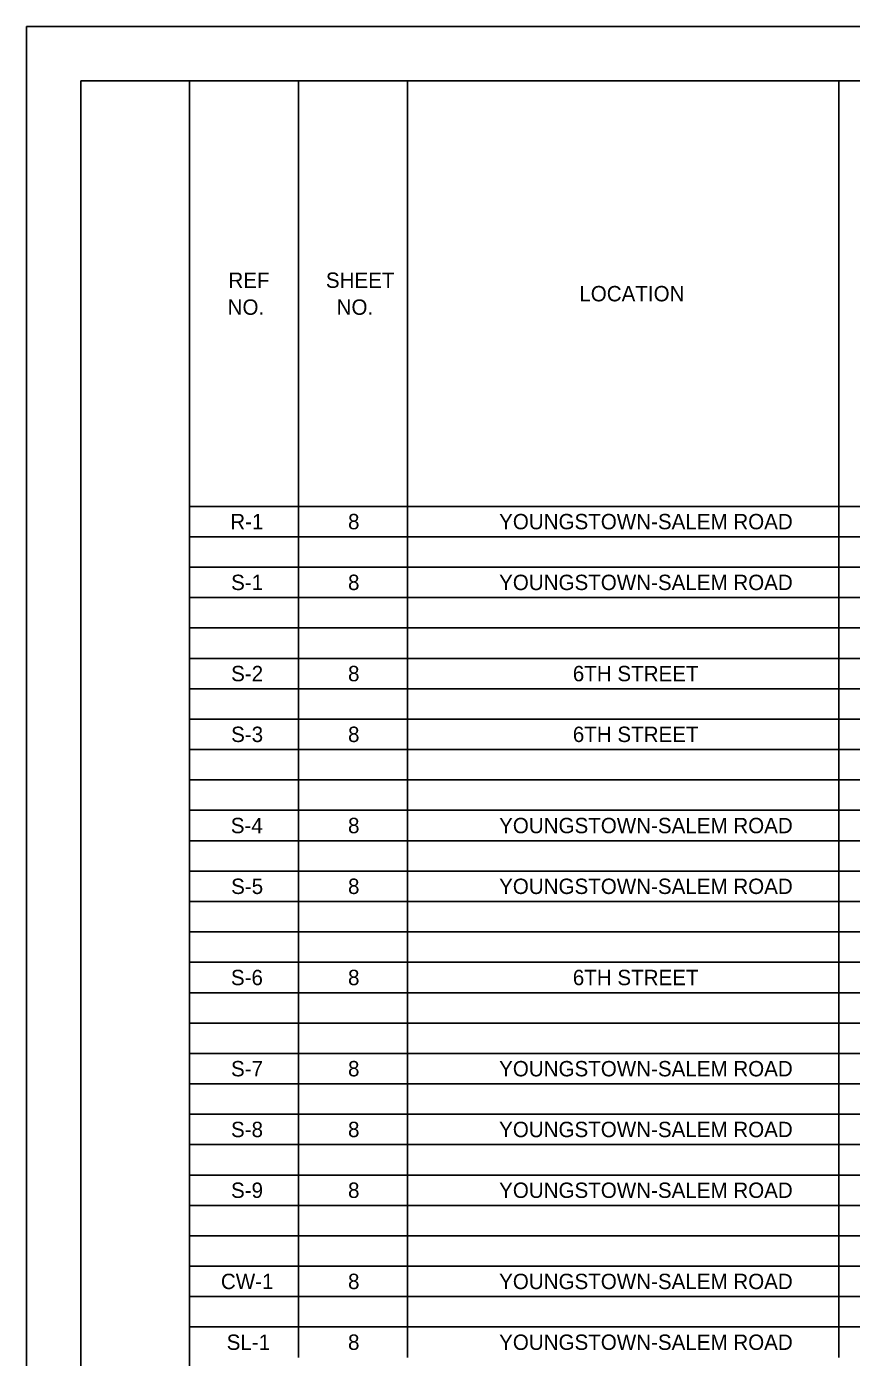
# Model space of a CAD drawing. Extents: x 0 to 34, y 0 to 22.
# Drawn here: x 0 to 7.6, y 9.74 to 22 of the extents above; entities that cross this region are included whole.
import ezdxf

# ---------------------------------------------------------------- set-up
doc = ezdxf.new("R2010")
doc.units = 0
for name, color, linetype in [('SH_Border', 7, 'Continuous'), ('SH_Cut_Line', 7, 'Continuous'), ('SH_Data', 7, 'Continuous')]:
    doc.layers.add(name, color=color, linetype=linetype)

msp = doc.modelspace()

# ---------------------------------------------------------------- linework, layer by layer
at = {"layer": 'SH_Border'}
for points in [[(0.5, 21.5), (1.5, 21.5), (1.5, 0.5), (0.5, 0.5)], [(1.5, 21.5), (33.5, 21.5), (33.5, 0.5), (1.5, 0.5)]]:
    msp.add_lwpolyline(points, close=True, dxfattribs=at)
at = {"layer": 'SH_Cut_Line'}
msp.add_lwpolyline([(0, 0), (34, 0), (34, 22), (0, 22)], close=True, dxfattribs=at)
at = {"layer": 'SH_Data'}
for p, q in [((1.5, 21.5), (8.951, 21.5)), ((1.5, 21.5), (1.5, 21.22)), ((2.504, 21.5), (2.504, 21.22)), ((3.508, 21.5), (3.508, 21.22)), ((7.484, 21.5), (7.484, 21.22)), ((1.5, 21.22), (1.5, 20.94)), ((2.504, 21.22), (2.504, 20.94)), ((3.508, 21.22), (3.508, 20.94)), ((7.484, 21.22), (7.484, 20.94)), ((1.5, 20.94), (1.5, 20.66)), ((2.504, 20.94), (2.504, 20.66)), ((3.508, 20.94), (3.508, 20.66)), ((7.484, 20.94), (7.484, 20.66)), ((1.5, 20.66), (1.5, 20.38)), ((2.504, 20.66), (2.504, 20.38)), ((3.508, 20.66), (3.508, 20.38)), ((7.484, 20.66), (7.484, 20.38)), ((1.5, 20.38), (1.5, 20.1)), ((2.504, 20.38), (2.504, 20.1)), ((3.508, 20.38), (3.508, 20.1)), ((7.484, 20.38), (7.484, 20.1)), ((1.5, 20.1), (1.5, 19.82)), ((2.504, 20.1), (2.504, 19.82)), ((3.508, 20.1), (3.508, 19.82)), ((7.484, 20.1), (7.484, 19.82)), ((1.5, 19.82), (1.5, 19.54)), ((2.504, 19.82), (2.504, 19.54)), ((3.508, 19.82), (3.508, 19.54)), ((7.484, 19.82), (7.484, 19.54)), ((1.5, 19.54), (1.5, 18.98)), ((2.504, 19.54), (2.504, 18.98)), ((3.508, 19.54), (3.508, 18.98)), ((7.484, 19.54), (7.484, 18.98)), ((1.5, 18.98), (1.5, 18.14)), ((2.504, 18.98), (2.504, 18.14)), ((3.508, 18.98), (3.508, 18.14)), ((7.484, 18.98), (7.484, 18.14)), ((1.5, 18.14), (1.5, 17.86)), ((2.504, 18.14), (2.504, 17.86)), ((3.508, 18.14), (3.508, 17.86)), ((7.484, 18.14), (7.484, 17.86)), ((1.5, 17.86), (1.5, 17.3)), ((2.504, 17.86), (2.504, 17.3)), ((3.508, 17.86), (3.508, 17.3)), ((7.484, 17.86), (7.484, 17.3)), ((1.5, 17.58), (8.951, 17.58)), ((1.5, 17.3), (8.951, 17.3)), ((1.5, 17.3), (1.5, 17.02)), ((2.504, 17.3), (2.504, 17.02)), ((3.508, 17.3), (3.508, 17.02)), ((7.484, 17.3), (7.484, 17.02)), ((1.5, 17.02), (8.951, 17.02)), ((1.5, 17.02), (1.5, 15.9)), ((2.504, 17.02), (2.504, 15.9)), ((3.508, 17.02), (3.508, 15.9)), ((7.484, 17.02), (7.484, 15.9)), ((1.5, 16.74), (8.951, 16.74)), ((1.5, 16.46), (8.951, 16.46)), ((1.5, 16.18), (8.951, 16.18)), ((1.5, 15.9), (8.951, 15.9)), ((1.5, 15.9), (1.5, 15.62)), ((2.504, 15.9), (2.504, 15.62)), ((3.508, 15.9), (3.508, 15.62)), ((7.484, 15.9), (7.484, 15.62)), ((1.5, 15.62), (8.951, 15.62)), ((1.5, 15.62), (1.5, 15.06)), ((2.504, 15.62), (2.504, 15.06)), ((3.508, 15.62), (3.508, 15.06)), ((7.484, 15.62), (7.484, 15.06)), ((1.5, 15.34), (8.951, 15.34)), ((1.5, 15.06), (8.951, 15.06)), ((1.5, 15.06), (1.5, 14.5)), ((2.504, 15.06), (2.504, 14.5)), ((3.508, 15.06), (3.508, 14.5)), ((7.484, 15.06), (7.484, 14.5)), ((1.5, 14.78), (8.951, 14.78)), ((1.5, 14.5), (8.951, 14.5)), ((1.5, 14.5), (1.5, 14.22)), ((2.504, 14.5), (2.504, 14.22)), ((3.508, 14.5), (3.508, 14.22)), ((7.484, 14.5), (7.484, 14.22)), ((1.5, 14.22), (8.951, 14.22)), ((1.5, 14.22), (1.5, 13.66)), ((2.504, 14.22), (2.504, 13.66)), ((3.508, 14.22), (3.508, 13.66)), ((7.484, 14.22), (7.484, 13.66)), ((1.5, 13.94), (8.951, 13.94)), ((1.5, 13.66), (8.951, 13.66)), ((1.5, 13.66), (1.5, 13.38)), ((2.504, 13.66), (2.504, 13.38)), ((3.508, 13.66), (3.508, 13.38)), ((7.484, 13.66), (7.484, 13.38)), ((1.5, 13.38), (8.951, 13.38)), ((1.5, 13.38), (1.5, 12.54)), ((2.504, 13.38), (2.504, 12.54)), ((3.508, 13.38), (3.508, 12.54)), ((7.484, 13.38), (7.484, 12.54)), ((1.5, 13.1), (8.951, 13.1)), ((1.5, 12.82), (8.951, 12.82)), ((1.5, 12.54), (8.951, 12.54)), ((1.5, 12.54), (1.5, 11.98)), ((2.504, 12.54), (2.504, 11.98)), ((3.508, 12.54), (3.508, 11.98)), ((7.484, 12.54), (7.484, 11.98)), ((1.5, 12.26), (8.951, 12.26)), ((1.5, 11.98), (8.951, 11.98)), ((1.5, 11.98), (1.5, 11.14)), ((2.504, 11.98), (2.504, 11.14)), ((3.508, 11.98), (3.508, 11.14)), ((7.484, 11.98), (7.484, 11.14)), ((1.5, 11.7), (8.951, 11.7)), ((1.5, 11.42), (8.951, 11.42)), ((1.5, 11.14), (8.951, 11.14)), ((1.5, 11.14), (1.5, 10.58)), ((2.504, 11.14), (2.504, 10.58)), ((3.508, 11.14), (3.508, 10.58)), ((7.484, 11.14), (7.484, 10.58)), ((1.5, 10.86), (8.951, 10.86)), ((1.5, 10.58), (8.951, 10.58)), ((1.5, 10.58), (1.5, 9.74)), ((2.504, 10.58), (2.504, 9.74)), ((3.508, 10.58), (3.508, 9.74)), ((7.484, 10.58), (7.484, 9.74)), ((1.5, 10.3), (8.951, 10.3)), ((1.5, 10.02), (8.951, 10.02))]:
    msp.add_line(p, q, dxfattribs=at)

# ---------------------------------------------------------------- texts
for s, height, p in [('REF', 0.1417, (1.859, 19.593)), ('SHEET', 0.1417, (2.757, 19.593)), ('LOCATION', 0.1417, (5.092, 19.469)), ('NO.', 0.1417, (1.852, 19.345)), ('NO.', 0.1417, (2.856, 19.345)), ('R-1', 0.1417, (1.876, 17.369)), ('8', 0.142, (2.961, 17.369)), ('YOUNGSTOWN-SALEM ROAD', 0.14167, (4.353, 17.369)), ('S-1', 0.1417, (1.884, 16.809)), ('8', 0.142, (2.961, 16.809)), ('YOUNGSTOWN-SALEM ROAD', 0.14167, (4.353, 16.809)), ('S-2', 0.1417, (1.884, 15.969)), ('8', 0.142, (2.961, 15.969)), ('6TH STREET', 0.1417, (5.032, 15.969)), ('S-3', 0.1417, (1.884, 15.409)), ('8', 0.142, (2.961, 15.409)), ('6TH STREET', 0.1417, (5.032, 15.409)), ('S-4', 0.1417, (1.881, 14.569)), ('8', 0.142, (2.961, 14.569)), ('YOUNGSTOWN-SALEM ROAD', 0.14167, (4.353, 14.569)), ('S-5', 0.1417, (1.884, 14.009)), ('8', 0.142, (2.961, 14.009)), ('YOUNGSTOWN-SALEM ROAD', 0.14167, (4.353, 14.009)), ('S-6', 0.1417, (1.882, 13.169)), ('8', 0.142, (2.961, 13.169)), ('6TH STREET', 0.1417, (5.032, 13.169)), ('S-7', 0.1417, (1.883, 12.329)), ('8', 0.142, (2.961, 12.329)), ('YOUNGSTOWN-SALEM ROAD', 0.14167, (4.353, 12.329)), ('S-8', 0.1417, (1.883, 11.769)), ('8', 0.142, (2.961, 11.769)), ('YOUNGSTOWN-SALEM ROAD', 0.14167, (4.353, 11.769)), ('S-9', 0.1417, (1.883, 11.209)), ('8', 0.142, (2.961, 11.209)), ('YOUNGSTOWN-SALEM ROAD', 0.14167, (4.353, 11.209)), ('CW-1', 0.1417, (1.79, 10.369)), ('8', 0.142, (2.961, 10.369)), ('YOUNGSTOWN-SALEM ROAD', 0.14167, (4.353, 10.369)), ('SL-1', 0.1417, (1.843, 9.809)), ('8', 0.142, (2.961, 9.809)), ('YOUNGSTOWN-SALEM ROAD', 0.14167, (4.353, 9.809))]:
    msp.add_text(s, height=height, dxfattribs=at).set_placement(p)

doc.saveas('drawing.dxf')
